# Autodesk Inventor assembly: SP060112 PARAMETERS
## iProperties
Created: 2012-06
Part Number: SP060112 PARAMETERS
Document SubType Name: Assembly
Designer: Administrator
DOOR_OPENING_WIDTH: 30.000 in
DOOR_OPENING_HEIGHT: 24.000 in
Author: Administrator
